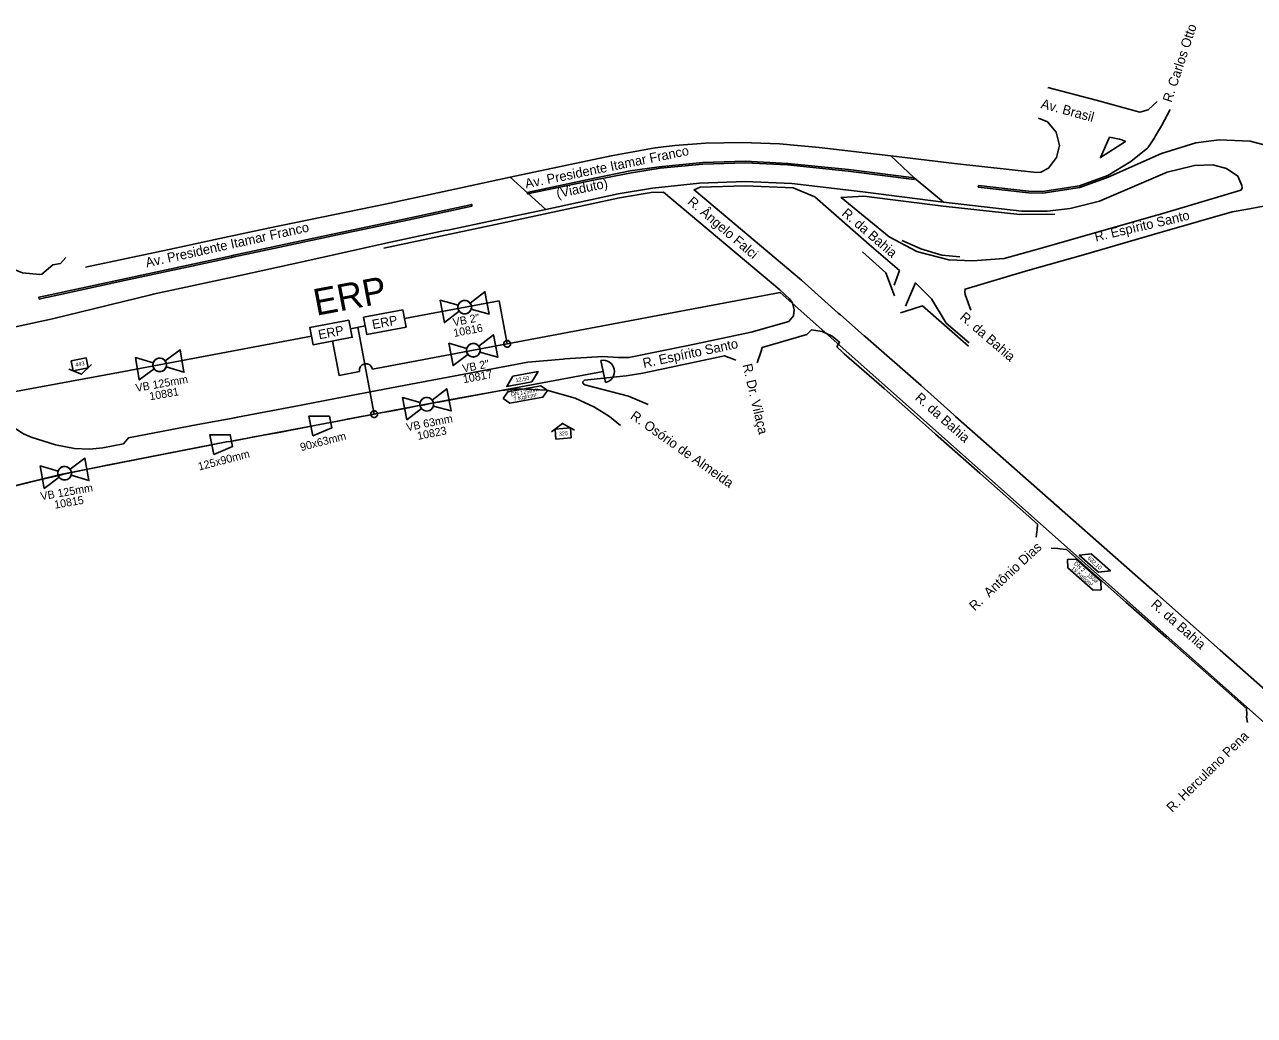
# Model space of a CAD drawing. Extents: x 656692 to 673945, y 7585994 to 7599066.
# Drawn here: x 671528 to 672450, y 7593332 to 7594075 of the extents above; entities that cross this region are included whole.
import ezdxf

# ---------------------------------------------------------------- set-up
doc = ezdxf.new("R2010")
doc.units = 0
for name, color, linetype in [('FORMATO', 7, 'Continuous'), ('LOGRADOURO', 7, 'Continuous'), ('LOGRADOURO_TEXTO', 7, 'Continuous'), ('MURETA', 7, 'Continuous'), ('NUM_REF', 7, 'Continuous'), ('SIMBOLO', 7, 'Continuous'), ('TEXTO', 7, 'Continuous'), ('TUBO_ACO_GN_2', 7, 'Continuous'), ('TUBO_PEAD_GN_125', 7, 'Continuous'), ('TUBO_PEAD_GN_63', 7, 'Continuous'), ('TUBO_PEAD_GN_90', 7, 'Continuous'), ('VALVULA_ACO_2', 7, 'Continuous'), ('VALVULA_PEAD_125', 7, 'Continuous'), ('VALVULA_PEAD_63', 7, 'Continuous'), ('VIADUTO', 7, 'Continuous')]:
    doc.layers.add(name, color=color, linetype=linetype)

# ---------------------------------------------------------------- blocks, each defined once
blk = doc.blocks.new('VALVULA_PEAD_DN_10')
at = {"layer": 'VALVULA_PEAD_125'}
for points in [[(-1.14, 0.57), (-4.25, 2.13), (-4.25, -2.13), (-1.14, -0.57)], [(-1.14, -0.57), (-4.25, -2.13), (-4.25, 2.13), (-1.14, 0.57)], [(1.14, -0.57), (4.25, -2.13), (4.25, 2.13), (1.14, 0.57)], [(1.14, -0.57), (4.25, -2.13), (4.25, 2.13), (1.14, 0.57)]]:
    blk.add_lwpolyline(points, dxfattribs=at)
blk.add_circle((0, 0), 1.28, dxfattribs=at)
for start, end in [(90, 270), (153.4349, 206.5651), (270, 90), (0, 26.5651), (333.4349, 0)]:
    blk.add_arc((0, 0), 1.28, start, end, dxfattribs=at)
blk = doc.blocks.new('VALVULA_PEAD_DN_9')
at = {"layer": 'VALVULA_PEAD_63'}
for points in [[(-1.14, 0.57), (-4.25, 2.13), (-4.25, -2.13), (-1.14, -0.57)], [(-1.14, -0.57), (-4.25, -2.13), (-4.25, 2.13), (-1.14, 0.57)], [(1.14, -0.57), (4.25, -2.13), (4.25, 2.13), (1.14, 0.57)], [(1.14, -0.57), (4.25, -2.13), (4.25, 2.13), (1.14, 0.57)]]:
    blk.add_lwpolyline(points, dxfattribs=at)
blk.add_circle((0, 0), 1.28, dxfattribs=at)
for start, end in [(90, 270), (153.4349, 206.5651), (270, 90), (0, 26.5651), (333.4349, 0)]:
    blk.add_arc((0, 0), 1.28, start, end, dxfattribs=at)
blk = doc.blocks.new('NUM_REF_1')
at = {"layer": 'NUM_REF'}
blk.add_lwpolyline([(-4.3125, 0.9375), (0, 3.75), (4.3125, 0.9375)], dxfattribs=at)
blk.add_lwpolyline([(2.875, -1.875), (2.875, 1.875), (-2.875, 1.875), (-2.875, -1.875)], close=True, dxfattribs=at)
blk = doc.blocks.new('VALVULA_ACO_3')
at = {"layer": 'VALVULA_ACO_2'}
for points in [[(-1.14, 0.57), (-4.25, 2.13), (-4.25, -2.13), (-1.14, -0.57)], [(-1.14, -0.57), (-4.25, -2.13), (-4.25, 2.13), (-1.14, 0.57)], [(1.14, -0.57), (4.25, -2.13), (4.25, 2.13), (1.14, 0.57)], [(1.14, -0.57), (4.25, -2.13), (4.25, 2.13), (1.14, 0.57)]]:
    blk.add_lwpolyline(points, dxfattribs=at)
blk.add_circle((0, 0), 1.28, dxfattribs=at)
for start, end in [(90, 270), (153.4349, 206.5651), (270, 90), (0, 26.5651), (333.4349, 0)]:
    blk.add_arc((0, 0), 1.28, start, end, dxfattribs=at)
blk = doc.blocks.new('INTERLIGACAO_5')
at = {"layer": 'SIMBOLO'}
blk.add_circle((0, 0), 1.28, dxfattribs=at)
for start, end in [(0, 180), (180, 0)]:
    blk.add_arc((0, 0), 1.28, start, end, dxfattribs=at)

msp = doc.modelspace()

# ---------------------------------------------------------------- linework, layer by layer
at = {"layer": 'LOGRADOURO'}
for points in [[(672295.23, 7594028), (672331.44, 7594018.59), (672364.11, 7594009.53), (672370.52, 7594011.4), (672377.17, 7594017.64)], [(672522.9, 7593967.77), (672446.99, 7593987.87), (672423.8, 7593988.93), (672406.34, 7593986.6), (672380.37, 7593978.49), (672340.57, 7593960.76), (672319.22, 7593952.95), (672291.38, 7593948.84), (672280.65, 7593949), (672243.01, 7593953.37), (672243.23, 7593954.67), (672280.73, 7593950.31), (672291.1, 7593950.15), (672318.86, 7593954.23), (672340.17, 7593962.09), (672357.49, 7593972.47), (672370.27, 7593982.92), (672375.3, 7593990.31), (672376.09, 7593991.87), (672380.58, 7593999.41), (672387.03, 7594011.64)], [(672288.28, 7594004.94), (672294.96, 7594002.25), (672301.5, 7593994.52), (672303.85, 7593984.67), (672301.69, 7593975.54), (672295.65, 7593967.59), (672289.94, 7593964.47), (672286.76, 7593964.3), (672225.1, 7593970.98), (672177.37, 7593976.81)], [(672216.95, 7593942.12), (672275.63, 7593935.29), (672294.61, 7593935.38), (672311.93, 7593937.27), (672333.88, 7593942.94), (672384.62, 7593964.65), (672403.24, 7593969.12), (672405.32, 7593969.49), (672418.94, 7593970.08), (672429.11, 7593967.36), (672437.76, 7593961.67), (672440.79, 7593954.68), (672441, 7593952.55), (672439.99, 7593951.03), (672436.61, 7593949.96), (672435.01, 7593949.51), (672400.68, 7593939.38), (672377.86, 7593932.61), (672375.96, 7593932.08), (672329.8, 7593918.89), (672286.83, 7593906.54), (672284.86, 7593905.96), (672262.57, 7593899.89), (672238.7, 7593898.07), (672220.88, 7593898.78), (672198.84, 7593904.53), (672196.98, 7593905.18), (672176.1, 7593915.98), (672140.18, 7593945.68), (672157.21, 7593946.47), (672216.62, 7593939), (672274.3, 7593932.76), (672300.37, 7593932.98)], [(671892.06, 7593960.88), (671841.21, 7593949.89), (671798.14, 7593940.53), (671711.76, 7593922.81), (671670.81, 7593913.99), (671634.92, 7593906.32), (671573.38, 7593893.4)], [(671933.04, 7593824.55), (671940.91, 7593825.14), (671961.35, 7593826.35), (671973.06, 7593825.51), (671981.07, 7593825.48), (672025.58, 7593834.65), (672072.8, 7593844.65), (672100.89, 7593852.56), (672104.53, 7593856.71), (672104.93, 7593861.43), (672103.65, 7593866.47), (672101.43, 7593869.52), (672094.32, 7593876.41), (672006.92, 7593949.49), (671997.74, 7593949.24), (671973.97, 7593945.22), (671881, 7593925.39), (671843.28, 7593917.35), (671797.22, 7593907.65)], [(672489.99, 7593548.46), (672424.46, 7593606.17), (672377.53, 7593647.75), (672320.64, 7593697.77), (672272.28, 7593740.65), (672225.98, 7593781.4), (672224.84, 7593782.46), (672200.2, 7593804.47), (672158.5, 7593841.01), (672157.45, 7593841.83), (672139.7, 7593857.5), (672137.99, 7593858.9), (672110.35, 7593883.67), (672029.97, 7593951.31), (672034.52, 7593953.33), (672068.34, 7593954.37), (672104.32, 7593952.73), (672120.38, 7593946.13), (672161.21, 7593910.34), (672183.88, 7593890.74), (672179.94, 7593879.77)], [(671719.2, 7593908.27), (671769.53, 7593918.95), (671816.11, 7593928.84), (671863.3, 7593939.1), (671863.18, 7593940.42), (671815.94, 7593930.08), (671769.44, 7593920.23), (671718.79, 7593909.46)], [(672702.09, 7593881.92), (672650.45, 7593898.24), (672649.08, 7593898.66), (672637.98, 7593902.35), (672635.81, 7593902.89), (672578.88, 7593920.7), (672576.66, 7593921.41), (672546.13, 7593931.05), (672521.95, 7593937.6), (672498.76, 7593940.85), (672480.63, 7593941.13), (672458.5, 7593939.43), (672456.86, 7593939.08), (672443.63, 7593936.69), (672433.45, 7593934.9), (672381.23, 7593919.91), (672379.43, 7593919.36), (672323.62, 7593903.15), (672278.46, 7593890.29), (672233.19, 7593876.92), (672232.96, 7593874.67), (672233.21, 7593872.84), (672237.5, 7593861.11)], [(671540.74, 7593888.17), (671539.18, 7593887.88), (671526.21, 7593889.11), (671514.92, 7593893.45), (671505.11, 7593899.41), (671495.99, 7593908.48), (671483.55, 7593933.43)], [(671918.68, 7593936.58), (671880.43, 7593928.66), (671845.31, 7593921.17), (671843.01, 7593920.71), (671798.84, 7593911.43), (671797.72, 7593911.11), (671786.42, 7593908.67), (671737.2, 7593897.49), (671680.33, 7593885.18), (671624.16, 7593873.09)], [(671718.79, 7593909.46), (671684.76, 7593902.21), (671683, 7593901.81), (671653.94, 7593895.64), (671600.35, 7593884.08), (671543.5, 7593871.87), (671538.46, 7593870.75), (671538.8, 7593869.39), (671543.84, 7593870.5), (671545.51, 7593870.89), (671599.15, 7593882.52)], [(672229.18, 7593900.97), (672215.63, 7593902.3), (672200.03, 7593906.97), (672186, 7593913.33)], [(671540.84, 7593888.19), (671549.06, 7593894.96), (671554.69, 7593896.08), (671558.73, 7593900.65)], [(671719.2, 7593908.27), (671685, 7593901), (671683.19, 7593900.57), (671654.27, 7593894.31), (671599.15, 7593882.52)], [(672156.27, 7593904.88), (672173.84, 7593889.16), (672180.3, 7593871.74)], [(672236.12, 7593836.47), (672219, 7593851.43), (672208.07, 7593869.52), (672195.89, 7593881.53), (672188.56, 7593864.06)], [(671624.16, 7593873.09), (671622.57, 7593872.69), (671548.63, 7593854.54), (671497.68, 7593843.45), (671451.36, 7593832.38), (671450.3, 7593831.13), (671450.45, 7593829.29), (671451.11, 7593828.48), (671492.83, 7593793.79), (671494.42, 7593792.5), (671511.29, 7593778.69), (671527.07, 7593768.3), (671532.67, 7593765.73), (671551.08, 7593760.16), (671565.13, 7593757.37), (671576.41, 7593756.87), (671586.59, 7593757.89), (671601.98, 7593760.89), (671605.66, 7593765.42), (671657.69, 7593775.27), (671685.38, 7593780.41), (671687.57, 7593780.78), (671729.87, 7593788.9)], [(672235.63, 7593834.08), (672201.21, 7593864.24), (672188, 7593860.13), (672184.83, 7593859.19)], [(672244.23, 7593738.81), (672210.97, 7593768.2), (672208.09, 7593770.79), (672199.03, 7593778.82), (672172.43, 7593802.25), (672142.59, 7593828.45), (672141.04, 7593829.88), (672137.05, 7593833.6), (672138.97, 7593837.03), (672133.37, 7593841.69), (672125.9, 7593845.12), (672117.91, 7593846.27), (672114.56, 7593842.84), (672080.95, 7593833.01), (672080.16, 7593830.43), (672077.13, 7593821.7)], [(671995.54, 7593790.32), (671980.67, 7593796.68), (671947.95, 7593805.2), (671946.96, 7593805.78), (671946.47, 7593806.42), (671946.44, 7593807.3), (671947.65, 7593808.5), (671978.94, 7593811.89), (671991.38, 7593813.78), (672052.82, 7593826.82), (672056.04, 7593825.65), (672058.79, 7593824.65), (672061.23, 7593823.56)], [(671933.04, 7593824.55), (671931.74, 7593824.45), (671905.29, 7593821.97), (671861.36, 7593813.71), (671817.43, 7593805.48), (671767.35, 7593796.04), (671729.87, 7593788.9)], [(671484.14, 7593720.45), (671530.07, 7593731.59), (671531.8, 7593732.01), (671555.53, 7593737.68), (671557.03, 7593738.06), (671589.7, 7593744.87), (671679.29, 7593762.24), (671682.13, 7593762.7), (671712.01, 7593768.22), (671765.16, 7593778.4), (671805.25, 7593785.96), (671847.6, 7593793.96), (671885.34, 7593800.95), (671898.79, 7593802.07), (671919.43, 7593801.12), (671940.67, 7593795.06), (671955.23, 7593788.33), (671966.36, 7593781.28), (671974.62, 7593774.63)], [(672286.48, 7593690.9), (672287, 7593694.88), (672287.12, 7593696.32), (672287.56, 7593700.58), (672244.23, 7593738.81)], [(672444.91, 7593551.89), (672444.3, 7593555.91), (672444.46, 7593557.89), (672444.24, 7593562.34), (672415.88, 7593587.4), (672383.89, 7593615.64), (672353.76, 7593642.18), (672309.1, 7593681.62), (672304.22, 7593682.13), (672302.73, 7593682.33), (672297.71, 7593682.64)]]:
    msp.add_lwpolyline(points, dxfattribs=at)
msp.add_lwpolyline([(672341.38, 7593990.85), (672334.68, 7593975.47), (672353.39, 7593987.67), (672350.62, 7593988.81), (672348.98, 7593989.29)], close=True, dxfattribs=at)
at = {"layer": 'MURETA'}
msp.add_lwpolyline([(672194.93, 7593959.14), (672145.42, 7593965.44), (672099.96, 7593969.99), (672068.57, 7593971.51), (672036.48, 7593970.51), (672004.55, 7593967.5), (671983, 7593964.18), (671955.83, 7593958.9), (671905.09, 7593948.28), (671904.81, 7593949.24), (671955.18, 7593960.13), (671981.87, 7593965.55), (672003.68, 7593968.56), (672036.35, 7593971.77), (672068.5, 7593972.74), (672100.32, 7593971.08), (672145.74, 7593966.57), (672194.96, 7593960.37), (672194.93, 7593959.14)], dxfattribs=at)
at = {"layer": 'SIMBOLO'}
for points in [[(671811.41, 7593861.27), (671782.03, 7593855.71), (671784.48, 7593842.81), (671813.85, 7593848.37)], [(671771.04, 7593853.63), (671741.66, 7593848.07), (671744.1, 7593835.18), (671773.48, 7593840.74)], [(671908.3, 7593807.26), (671889.4, 7593803.76), (671894.07, 7593811.49), (671912.97, 7593814.99)], [(671744.01, 7593766.87), (671758.14, 7593772.73), (671756.39, 7593781.56), (671741.09, 7593781.58)], [(671669.65, 7593752.91), (671683.78, 7593758.78), (671682.03, 7593767.6), (671666.73, 7593767.63)], [(672333.13, 7593664.56), (672318.77, 7593677.33), (672327.74, 7593678.39), (672342.1, 7593665.62)]]:
    msp.add_lwpolyline(points, close=True, dxfattribs=at)
for points in [[(671886.61, 7593794.73), (671890.11, 7593799.83), (671914.94, 7593804.43), (671920.04, 7593800.92), (671916.54, 7593795.83), (671891.71, 7593791.22), (671886.61, 7593794.73)], [(672335.34, 7593651.4), (672329.16, 7593651.04), (672310.29, 7593667.81), (672309.92, 7593673.99), (672316.1, 7593674.35), (672334.97, 7593657.58), (672335.34, 7593651.4)]]:
    msp.add_lwpolyline(points, dxfattribs=at)
at = {"layer": 'TUBO_ACO_GN_2'}
for p, q in [((671889.78, 7593835.81), (672094.43, 7593874.29)), ((672094.43, 7593874.29), (672704.33, 7593332.18)), ((671812.63, 7593854.82), (671883.69, 7593868.18)), ((671883.69, 7593868.18), (671889.78, 7593835.81)), ((671788.77, 7593816.82), (671889.78, 7593835.81))]:
    msp.add_line(p, q, dxfattribs=at)
msp.add_lwpolyline([(671758.78, 7593837.96), (671763.65, 7593812.1), (671778.94, 7593814.97)], dxfattribs=at)
msp.add_arc((671783.85, 7593815.89), 5, 10.64901, 190.64901, dxfattribs=at)
at = {"layer": 'TUBO_PEAD_GN_125'}
for points in [[(671492.16, 7593794.74), (671598.29, 7593814.25), (671742.9, 7593841.52)], [(671668.3, 7593760.12), (671642.58, 7593755.11), (671554.63, 7593737.75), (671451.79, 7593712.64), (671424.78, 7593705.89), (671402.48, 7593700.82), (671380.29, 7593695.35), (671355.56, 7593689.27), (671339.01, 7593685.4), (671311.38, 7593678.45), (671129.36, 7593634.65), (671064.63, 7593619.35), (671014.95, 7593607.29)]]:
    msp.add_lwpolyline(points, dxfattribs=at)
at = {"layer": 'TUBO_PEAD_GN_63'}
for p, q in [((671772.26, 7593847.19), (671783.25, 7593849.26)), ((671790.04, 7593783.09), (671777.75, 7593848.22)), ((671963.38, 7593806.74), (671959.97, 7593823.4))]:
    msp.add_line(p, q, dxfattribs=at)
msp.add_lwpolyline([(671757.31, 7593776.9), (671763.94, 7593778.16), (671769.72, 7593779.25), (671775.03, 7593780.26), (671780.33, 7593781.25), (671784.98, 7593782.12), (671790.03, 7593783.09), (671796.08, 7593784.24), (671801.13, 7593785.2), (671812.98, 7593787.39), (671822.62, 7593789.24), (671827.87, 7593790.2), (671831.04, 7593790.82), (671834.46, 7593791.48), (671838.1, 7593792.16), (671961.67, 7593815.07)], dxfattribs=at)
msp.add_arc((671961.67, 7593815.07), 8.51, 281.54378, 101.54378, dxfattribs=at)
at = {"layer": 'TUBO_PEAD_GN_90'}
msp.add_lwpolyline([(671682.95, 7593762.85), (671686.8, 7593763.51), (671693.84, 7593764.86), (671699.74, 7593765.97), (671704.23, 7593766.76), (671719.87, 7593769.61), (671741.57, 7593773.86), (671742.58, 7593774.06)], dxfattribs=at)
at = {"layer": 'VIADUTO'}
msp.add_lwpolyline([(671967.64, 7593976.78), (672000.79, 7593982.84), (672015.37, 7593984.53), (672038.43, 7593986.34), (672065.85, 7593986.89), (672093.89, 7593985.88), (672123.65, 7593983.19), (672177.37, 7593976.81), (672194.96, 7593960.37), (672216.95, 7593942.12), (672156.41, 7593949.75), (672103.14, 7593956.01), (672068.18, 7593957.45), (672033.95, 7593956.36), (671998.66, 7593952.55), (671972.93, 7593948.25), (671918.68, 7593936.58), (671892.06, 7593960.88)], close=True, dxfattribs=at)

# ---------------------------------------------------------------- block references
at = {"layer": 'FORMATO', "xscale": 2, "yscale": 2}
for p, rotation in [((671569.1, 7593820.41), -168.7575551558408), ((671931.76, 7593768.62), 4.39985724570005)]:
    msp.add_blockref('NUM_REF_1', p, dxfattribs=dict(at, rotation=rotation))
at = {"layer": 'SIMBOLO', "xscale": 2, "yscale": 2, "rotation": -14.764722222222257}
for p in [(671889.78, 7593835.81), (671790.03, 7593783.09)]:
    msp.add_blockref('INTERLIGACAO_5', p, dxfattribs=at)
at = {"layer": 'VALVULA_ACO_2', "xscale": 4, "yscale": 4, "rotation": 10.65137730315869}
for p in [(671857.85, 7593863.32), (671864.35, 7593831.03)]:
    msp.add_blockref('VALVULA_ACO_3', p, dxfattribs=at)
at = {"layer": 'VALVULA_PEAD_125'}
for p, xscale, yscale, rotation in [((671629.1, 7593820.06), 3.9999999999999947, 3.9999999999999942, 9.855788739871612), ((671557.8, 7593738.76), 3.999999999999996, 3.999999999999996, 9.85578873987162)]:
    msp.add_blockref('VALVULA_PEAD_DN_10', p, dxfattribs=dict(at, xscale=xscale, yscale=yscale, rotation=rotation))
at = {"layer": 'VALVULA_PEAD_63', "xscale": 4, "yscale": 4, "rotation": 11.229767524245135}
msp.add_blockref('VALVULA_PEAD_DN_9', (671829.45, 7593790.51), dxfattribs=at)

# ---------------------------------------------------------------- texts
for s, height, rotation, p in [('VB 2"', 6, 10.65138, (671849.52, 7593848.99)), ('10816', 6, 10.65138, (671849.95, 7593840.93)), ('443', 3, 10.77081, (671566.14, 7593818.57)), ('VB 2"', 6, 10.65138, (671856.73, 7593814.34)), ('VB 125mm', 6, 9.85579, (671611.59, 7593799.77)), ('10817', 6, 10.65138, (671857.15, 7593806.27)), ('10881', 6, 9.85579, (671621.9, 7593793.44)), ('VB 63mm', 6, 11.22977, (671814.72, 7593770.25)), ('10823', 6, 11.22977, (671822.9, 7593763.72)), ('325', 3, 4.39986, (671928.56, 7593766.87)), ('VB 125mm', 6, 9.85579, (671540.28, 7593718.46)), ('10815', 6, 9.85579, (671550.6, 7593712.13))]:
    msp.add_text(s, height=height, rotation=rotation).set_placement(p)
at = {"layer": 'LOGRADOURO_TEXTO'}
for s, rotation, p in [('R. Carlos Otto', 71.83108, (672387.98, 7594016.35)), ('Av. Brasil', 344.98655, (672289.5, 7594012.72)), ('Av. Presidente Itamar Franco', 11.60657, (671903.88, 7593952.32)), ('(Viaduto)', 11.87726, (671927.46, 7593945.02)), ('R. Ângelo Falci ', 319.45551, (672024.47, 7593941.45)), ('R. da Bahia ', 319.45551, (672140.11, 7593932.72)), ('R. Espírito Santo', 13.18952, (672331.23, 7593912.48)), ('Av. Presidente Itamar Franco', 12.45245, (671619.36, 7593893.12)), ('R. da Bahia ', 319.45551, (672228.63, 7593854.86)), ('R. Espírito Santo', 11.98314, (671992.21, 7593817.71)), ('R. Dr. Vilaça', 283.18206, (672066.18, 7593820.05)), ('R. da Bahia ', 318.58403, (672195.08, 7593794.5)), ('R. Osório de Almeida', 324.76518, (671981.55, 7593780.29)), ('R.  Antônio Dias', 42.9138, (672240.3, 7593635.13)), ('R. da Bahia ', 318.58403, (672371.99, 7593639.51)), ('R. Herculano Pena', 44.47577, (672388.51, 7593484))]:
    msp.add_text(s, height=7.2, rotation=rotation, dxfattribs=at).set_placement(p)
at = {"layer": 'TEXTO'}
for s, height, rotation, p in [('ERP', 20, 10.71877, (671746.55, 7593856.8)), ('ERP', 7, 10.71877, (671789.12, 7593846.81)), ('ERP', 7, 10.71877, (671748.75, 7593839.17)), ('12,50', 3, 10.50245, (671896.3, 7593806.95)), ('DN 125mm', 3, 10.50245, (671892.81, 7593796.39)), ('7 Kgf/cm²', 3, 10.50245, (671894.77, 7593792.96)), ('90x63mm', 6, 14.58512, (671735.32, 7593755.31)), ('125x90mm', 6, 14.58512, (671658.7, 7593740.77)), ('DN 2 - 150#', 3, 318.36725, (672314.45, 7593670.65)), ('632,10', 3, 318.36725, (672324.65, 7593674.61)), ('19 Kgf/cm²', 3, 318.36725, (672312.53, 7593666.99))]:
    msp.add_text(s, height=height, rotation=rotation, dxfattribs=at).set_placement(p)

doc.saveas('drawing.dxf')
